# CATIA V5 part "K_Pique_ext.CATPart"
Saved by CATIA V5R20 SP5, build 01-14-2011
Part number: Pique_ext
Bounding box of the stored display mesh (mm): x -10 to 10, y 0 to 300, z -9.985 to 11
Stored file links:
  G:\Khaled_CFAO_2011\ST2M\ST2M_GR2\amorin\Khaled\CAD_Modification\K_Pique_ext.CATPart
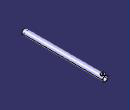
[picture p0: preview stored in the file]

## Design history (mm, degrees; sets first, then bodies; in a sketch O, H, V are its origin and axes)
Parameters
  `Diametre-pique_int` = 0
Body1 (main body)
  Sketch1 on zx-plane, origin (0, 0, 0), H (-1, 0, 0), V (0, 0, 1)
    circle A1 centre (0, 0) radius 10
  Pad1: profile Sketch1, direction (0, 1, 0), length 300
  Sketch2 on xy-plane, origin (0, 0, 0), H (1, 0, 0), V (0, 1, 0)
    circle A1 centre (0, 291) radius 7
    point P1 (0, 291)
    reference projected line E1 (-10, 300) -> (10, 300) from edge [face of Pad1 from Sketch1.A1 | end face of Pad1]
    distance P1 E1 = 9
    coincidence: P1 V
  Pad2: profile Sketch2, direction (0, 0, 1), length 11
  Sketch3 on end face of Pad1, origin (0, 300, 0), H (1, 0, 0), V (0, 0, -1)
    point P1 (0, 0)
  Hole1: placed by Sketch3, at (0, 300, 0) direction (0, -1, 0), diameter 16, depth 300, counterbore diameter 18, counterbore depth 290
  Sketch4 on end face of Pad2, origin (0, 291, 11), H (1, 0, 0), V (0, 1, 0)
    point P1 (0, 0)
  Hole2: placed by Sketch4, at (0, 291, 11) direction (0, 0, -1), diameter 5, through (limit type 6), threaded, thread diameter 5.5, thread depth 2.3682, pitch 1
